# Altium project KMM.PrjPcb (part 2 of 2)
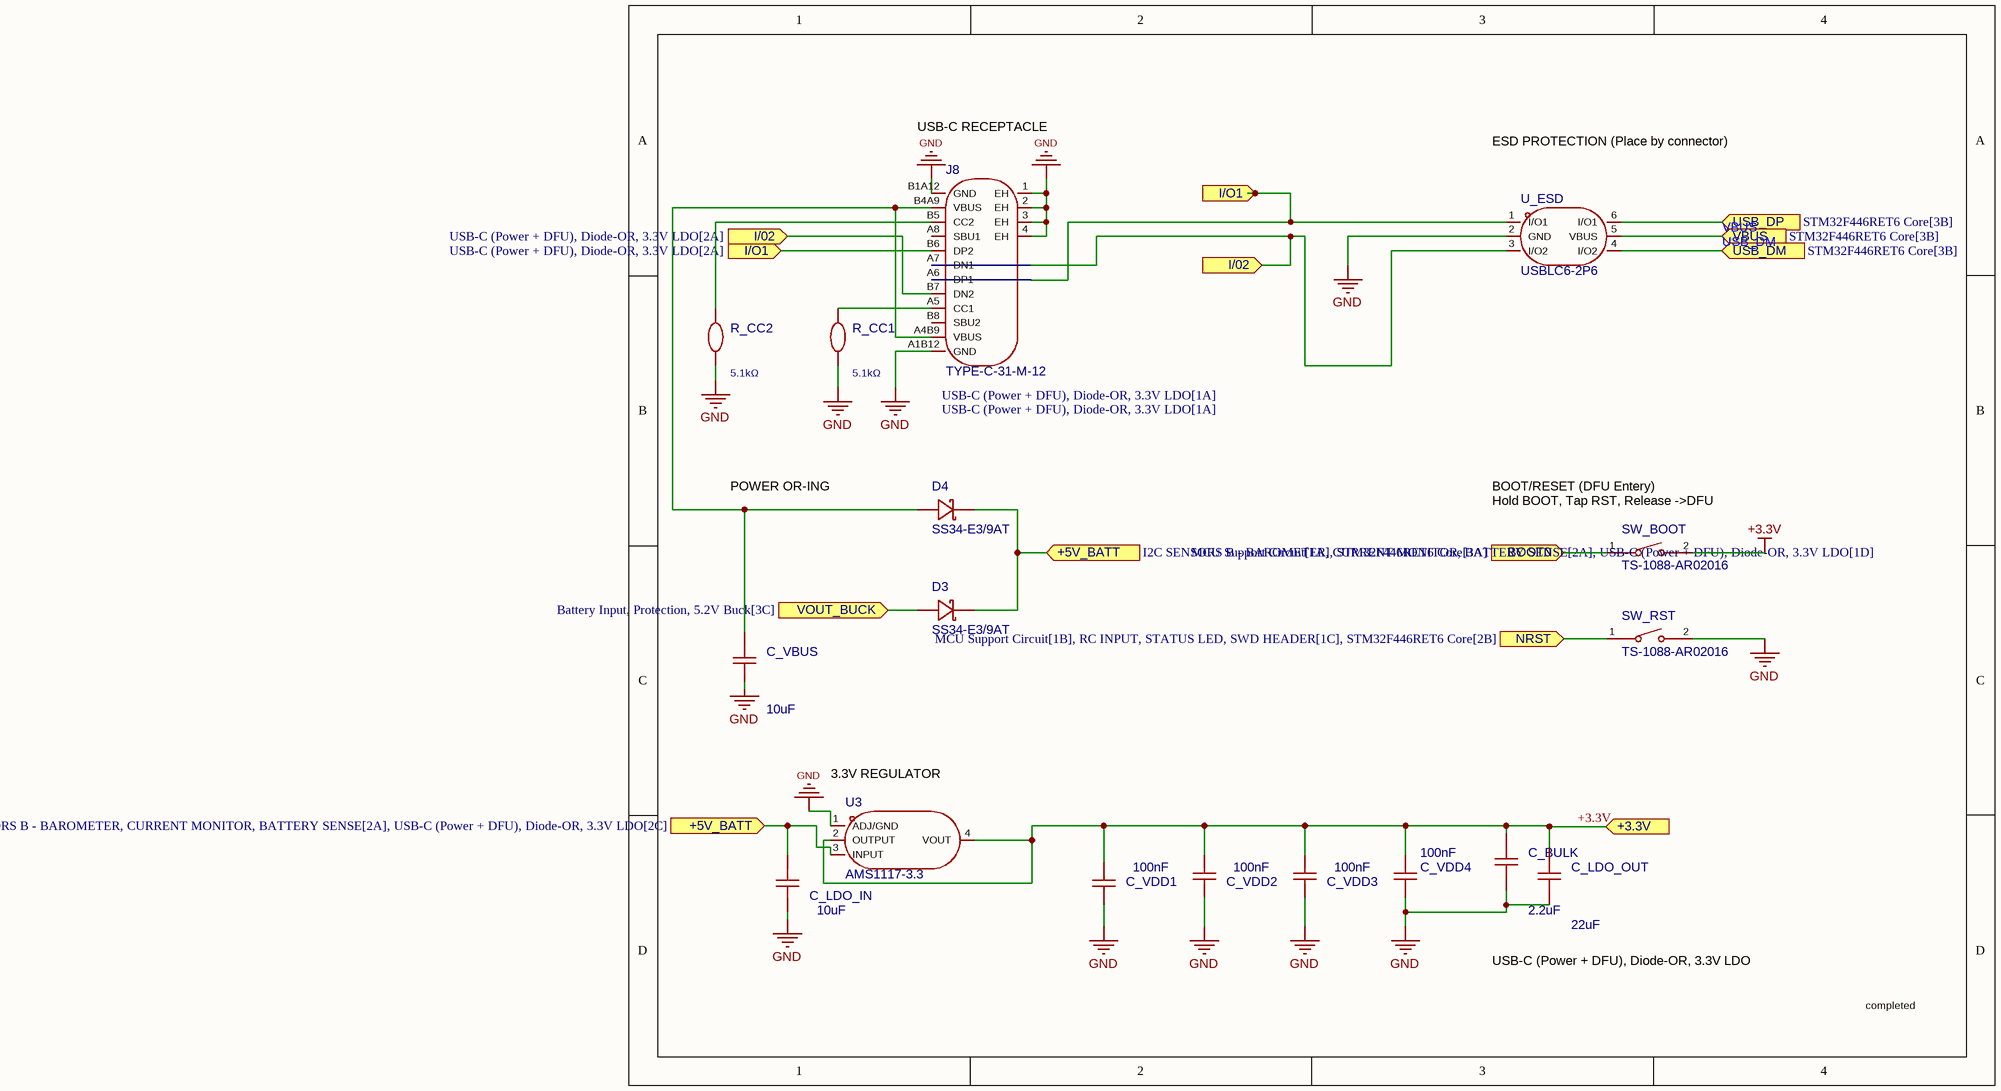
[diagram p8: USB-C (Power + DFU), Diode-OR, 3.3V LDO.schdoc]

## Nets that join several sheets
+3.3V: I2C Sensors A- IMU and Magnetometer (9 pins), I2C SENSORS B - BAROMETER, CURRENT MONITOR, BATTERY SENSE (8 pins), MCU Support Circuit (FB2.1 R_NRST.1), RC INPUT, STATUS LED, SWD HEADER (J_SWD.1 R21.1), STM32F446RET6 Core (5 pins), USB-C (Power + DFU), Diode-OR, 3.3V LDO (9 pins)
GND: Battery Input, Protection, 5.2V Buck (13 pins), EXTERNAL CONNECTORS (9 pins), I2C Sensors A- IMU and Magnetometer (12 pins), I2C SENSORS B - BAROMETER, CURRENT MONITOR, BATTERY SENSE (12 pins), MCU Support Circuit (9 pins), RC INPUT, STATUS LED, SWD HEADER (C22.2 J_SWD.3 Q2.2 U10.3), STM32F446RET6 Core (5 pins), USB-C (Power + DFU), Diode-OR, 3.3V LDO (19 pins)
+5V_SYS: EXTERNAL CONNECTORS (C_LORA.1 J4.1 J5.1 J7.6), I2C SENSORS B - BAROMETER, CURRENT MONITOR, BATTERY SENSE (U7.2), RC INPUT, STATUS LED, SWD HEADER (D5.1)
BOOT0: MCU Support Circuit (R_BOOT.1), STM32F446RET6 Core (U1.60), USB-C (Power + DFU), Diode-OR, 3.3V LDO (SW_BOOT.1)
GPS_RX: EXTERNAL CONNECTORS (J5.4), STM32F446RET6 Core (U1.54)
GPS_TX: EXTERNAL CONNECTORS (J5.3), STM32F446RET6 Core (U1.53)
I2C1_SCL: I2C Sensors A- IMU and Magnetometer (R4.2 U4.23 U5.1), I2C SENSORS B - BAROMETER, CURRENT MONITOR, BATTERY SENSE (U6.4 U7.6), STM32F446RET6 Core (U1.61)
I2C1_SDA: I2C Sensors A- IMU and Magnetometer (R2.2 U4.24 U5.16), I2C SENSORS B - BAROMETER, CURRENT MONITOR, BATTERY SENSE (U6.3 U7.5), STM32F446RET6 Core (U1.62)
LORA_AUX: EXTERNAL CONNECTORS (J7.5), STM32F446RET6 Core (U1.41)
LORA_M0: EXTERNAL CONNECTORS (J7.1), STM32F446RET6 Core (U1.24)
LORA_M1: EXTERNAL CONNECTORS (J7.2), STM32F446RET6 Core (U1.25)
LORA_RX: EXTERNAL CONNECTORS (J7.4), STM32F446RET6 Core (U1.52)
LORA_TX: EXTERNAL CONNECTORS (J7.3), STM32F446RET6 Core (U1.51)
NetC1_1: Battery Input, Protection, 5.2V Buck (6 pins), I2C SENSORS B - BAROMETER, CURRENT MONITOR, BATTERY SENSE (R6.1)
NetC5_1: Battery Input, Protection, 5.2V Buck (C5.1 C6.1 L1.2 R5.1), USB-C (Power + DFU), Diode-OR, 3.3V LDO (D3.2)
NetC_LDO_IN_1: I2C SENSORS B - BAROMETER, CURRENT MONITOR, BATTERY SENSE (U7.1), USB-C (Power + DFU), Diode-OR, 3.3V LDO (C_LDO_IN.1 D3.1 D4.1 U3.3)
NetC_VDDA1_1: MCU Support Circuit (C_VDDA1.1 C_VDDA2.1 FB2.2), STM32F446RET6 Core (U1.13)
NetJ_BAT_1: Battery Input, Protection, 5.2V Buck (Q1.3), EXTERNAL CONNECTORS (J_BAT.1)
NetJ_SWD_2: RC INPUT, STATUS LED, SWD HEADER (J_SWD.2), STM32F446RET6 Core (U1.49)
NetJ_SWD_4: RC INPUT, STATUS LED, SWD HEADER (J_SWD.4), STM32F446RET6 Core (U1.46)
NetQ2_3: RC INPUT, STATUS LED, SWD HEADER (Q2.3 R21.2), STM32F446RET6 Core (U1.43)
NetU1_45: STM32F446RET6 Core (U1.45), USB-C (Power + DFU), Diode-OR, 3.3V LDO (U_ESD.6)
NRST: MCU Support Circuit (C_NRST.1 R_NRST.2), RC INPUT, STATUS LED, SWD HEADER (J_SWD.5), STM32F446RET6 Core (U1.7), USB-C (Power + DFU), Diode-OR, 3.3V LDO (SW_RST.1)
OSC_IN: MCU Support Circuit (C8.1 Y1.1), STM32F446RET6 Core (U1.5)
OSC_OUT: MCU Support Circuit (C7.1 Y1.3), STM32F446RET6 Core (U1.6)
SBUS_IN: EXTERNAL CONNECTORS (J4.3), RC INPUT, STATUS LED, SWD HEADER (R20.2)
TIM2_CH1: EXTERNAL CONNECTORS (J_M1.3), STM32F446RET6 Core (U1.14)
TIM2_CH2: EXTERNAL CONNECTORS (J_M2.3), STM32F446RET6 Core (U1.15)
TIM2_CH3: EXTERNAL CONNECTORS (J_M3.3), STM32F446RET6 Core (U1.16)
TIM2_CH4: EXTERNAL CONNECTORS (J_M4.3), STM32F446RET6 Core (U1.17)
USB_DM: STM32F446RET6 Core (U1.44), USB-C (Power + DFU), Diode-OR, 3.3V LDO (U_ESD.4)
VBAT_SENSE: I2C SENSORS B - BAROMETER, CURRENT MONITOR, BATTERY SENSE (C14.1 R6.2 R7.1), STM32F446RET6 Core (U1.8)
VBUS: STM32F446RET6 Core (U1.42), USB-C (Power + DFU), Diode-OR, 3.3V LDO (U_ESD.5)
VCAP: MCU Support Circuit (C_VCAP.1), STM32F446RET6 Core (U1.30)
WS2812: RC INPUT, STATUS LED, SWD HEADER (R25.2), STM32F446RET6 Core (U1.26)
